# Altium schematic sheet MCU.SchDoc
size A4
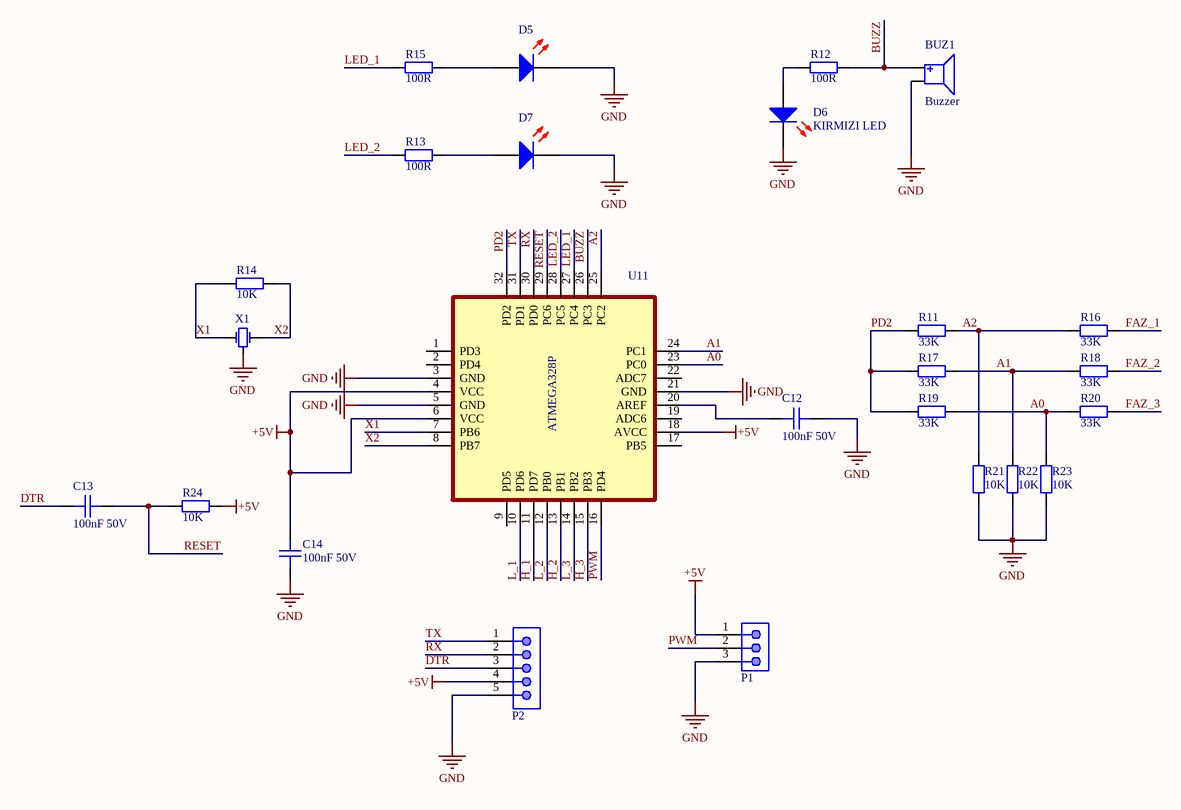
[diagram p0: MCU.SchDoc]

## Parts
BUZ1  Deger: Buzzer  [BUZ: CMT-7525]  (hidden comment: BUZZER MAGN 3.6V 7.5X7.5MM SMD)
C12  Deger: 100nF 50V  [CAP 0805/2012]  (hidden comment: CAP CER 0.1UF 50V X7R 0805)
C13  Deger: 100nF 50V  [CAP 0805/2012]  (hidden comment: CAP CER 0.1UF 50V X7R 0805)
C14  Deger: 100nF 50V  [CAP 0805/2012]  (hidden comment: CAP CER 0.1UF 50V X7R 0805)
D5  Red 645nm LED Indication - Discrete 1.8V 0805  [SMD: LED 0805/2012 RED]  (value not drawn)
D6  Deger: KIRMIZI LED  [SMD: LED 0805/2012 RED]  (hidden comment: Red 645nm LED Indication - Discrete 1.8V 0805)
D7  Red 645nm LED Indication - Discrete 1.8V 0805  [SMD: LED 0805/2012 RED]  (value not drawn)
P1  WR-PHD 2.54 mm Angled Socket Header  [PWM_CONN]  (value not drawn)
P2  WR-PHD 2.54 mm Angled Socket Header  [TTL_CONN_5]  (value not drawn)
R11  Deger: 33K  [RES_0805]  (hidden comment: RES SMD 33K OHM 1% 1/8W 0805)
R12  Deger: 100R  [RES_0805]  (hidden comment: RES SMD 100 OHM 1% 1/8W 0805)
R13  Deger: 100R  [RES_0805]  (hidden comment: RES SMD 100 OHM 1% 1/8W 0805)
R14  Deger: 10K  [RES_0805]  (hidden comment: RES SMD 10K OHM 1% 1/8W 0805)
R15  Deger: 100R  [RES_0805]  (hidden comment: RES SMD 100 OHM 1% 1/8W 0805)
R16  Deger: 33K  [RES_0805]  (hidden comment: RES SMD 33K OHM 1% 1/8W 0805)
R17  Deger: 33K  [RES_0805]  (hidden comment: RES SMD 33K OHM 1% 1/8W 0805)
R18  Deger: 33K  [RES_0805]  (hidden comment: RES SMD 33K OHM 1% 1/8W 0805)
R19  Deger: 33K  [RES_0805]  (hidden comment: RES SMD 33K OHM 1% 1/8W 0805)
R20  Deger: 33K  [RES_0805]  (hidden comment: RES SMD 33K OHM 1% 1/8W 0805)
R21  Deger: 10K  [RES_0805]  (hidden comment: RES SMD 10K OHM 1% 1/8W 0805)
R22  Deger: 10K  [RES_0805]  (hidden comment: RES SMD 10K OHM 1% 1/8W 0805)
R23  Deger: 10K  [RES_0805]  (hidden comment: RES SMD 10K OHM 1% 1/8W 0805)
R24  Deger: 10K  [RES_0805]  (hidden comment: RES SMD 10K OHM 1% 1/8W 0805)
U11  IC MCU 8BIT 32KB FLASH 32TQFP  [TQFP32]  (value not drawn)
X1  CERAMIC RES 16.0000MHZ 15PF SMD  [CRYSTAL_16MHZ(CTSE16)]  (value not drawn)

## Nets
+5V: C14.1 P1.1 P2.4 R24.2 U11.4(VCC) U11.6(VCC) U11.18(AVCC)
GND: BUZ1.2(Negative) C12.2 C14.2 D5.2(K) D6.2(K) D7.2(K) P1.3 P2.5 R21.1 R22.1 R23.1 U11.3(GND) U11.5(GND) U11.21(GND) X1.2(GND)
A0: R19.2 R20.1 R23.2 U11.23(PC0)
A1: R17.2 R18.1 R22.2 U11.24(PC1)
A2: R11.2 R16.1 R21.2 U11.25(PC2)
BUZZ: BUZ1.1(Positive) R12.2 U11.26(PC3)
DTR: C13.1 P2.3
FAZ_1: R16.2
FAZ_2: R18.2
FAZ_3: R20.2
H_1: U11.11(PD7)
H_2: U11.13(PB1)
H_3: U11.15(PB3)
L_1: U11.10(PD6)
L_2: U11.12(PB0)
L_3: U11.14(PB2)
LED_1: R15.1 U11.27(PC4)
LED_2: R13.1 U11.28(PC5)
PD2: R11.1 R17.1 R19.1 U11.32(PD2)
PWM: P1.2 U11.16(PD4)
RESET: C13.2 R24.1 U11.29(PC6)
RX: P2.2 U11.30(PD0)
TX: P2.1 U11.31(PD1)
X1: R14.1 U11.7(PB6) X1.1(OSC1)
X2: R14.2 U11.8(PB7) X1.3(OSC2)
NetC12_1: C12.1 U11.20(AREF)
NetD5_1: D5.1(A) R15.2
NetD6_1: D6.1(A) R12.1
NetD7_1: D7.1(A) R13.2

Not connected (* = marked no-connect by the designer): U11 1(PD3) 2(PD4) 9(PD5) 17(PB5) 19(ADC6) 22(ADC7)

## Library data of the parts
BUZ1 = Buzzer(CMT-7525-80-SMT-TR): Buzzers Transducer, Externally Driven Magnetic 3.6V 100mA 2.73kHz 80dB @ 3.6V, 10cm Surface Mount Solder Pads; Kılıf: Nonstandard; -Sicaklik: -40; +Sicaklik: +85
C12-C14 = 100nF 50V 0805: 0.1µF ±10% 50V Ceramic Capacitor X7R 0805 (2012 Metric); Kılıf: 0805; Cins: Kondansator; Uretici Kodu: CL21B104KBCNNNC; -Sicaklik: -55; +Sicaklik: +125; Lehim Yöntemi: SMD
D5 D7 = LED_Kırmızı: LED RED DIFFUSED 0805 SMD; Uretici Kodu: LH R974-LP-1; Kılıf: 0805; -Sicaklik: -40; +Sicaklik: +125; Deger: KIRMIZI LED
D6 = LED_Kırmızı: LED RED DIFFUSED 0805 SMD; Uretici Kodu: LH R974-LP-1; Kılıf: 0805; -Sicaklik: -40; +Sicaklik: +125
P1 = HDR(1X3): Cins: Konnektor; Uretici Kodu: 613003143121; Kılıf: 3POS 2.54MM; -Sicaklik: -40; +Sicaklik: +105; Lehim Yöntemi: MANUEL
P2 = HDR(1X5): Cins: Konnektor; Uretici Kodu: 613005143121; Kılıf: 5POS 2.54MM; -Sicaklik: -40; +Sicaklik: +105; Lehim Yöntemi: MANUEL
R11 R16-R20 = 33K 0805: 33 kOhms ±1% 0.125W, 1/8W Chip Resistor 0805 (2012 Metric) Moisture Resistant Thick Film; Cins: Direnc; Kılıf: 0805; -Sicaklik: -55; +Sicaklik: +155; Uretici Kodu: RC0805FR-0733KL
R12 R13 R15 = 100R 0805: 100 Ohms ±1% 0.125W, 1/8W Chip Resistor 0805 (2012 Metric) Moisture Resistant Thick Film; Cins: Direnc; Uretici Kodu: RC0805FR-07100RL; Kılıf: 0805; -Sicaklik: -55; +Sicaklik: +155
R14 R21-R24 = 10K 0805: 10 kOhms ±1% 0.125W, 1/8W Chip Resistor 0805 (2012 Metric) Moisture Resistant Thick Film; Cins: Direnc; Kılıf: 0805; Uretici Kodu: RC0805FR-0710KL; -Sicaklik: -55; +Sicaklik: +155
U11 = ATMEGA328P: AVR AVR® ATmega Microcontroller IC 8-Bit 20MHz 32KB (16K x 16) FLASH 32-TQFP (7x7); Uretici Kodu: RC0805FR-07100RL; -Sicaklik: -40; +Sicaklik: +85; Lehim Yöntemi: SMD
X1 = CRYSTAL 16.0000MHZ(CSTCE16M0V53-R0): 16MHz Ceramic Resonator Built in Capacitor 15pF ±0.3%  -20°C ~ 80°C Surface Mount; Cins: Kristal; Kılıf: 3-SMD; -Sicaklik: -20; +Sicaklik: +80; Deger: 16 MHZ 15PF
